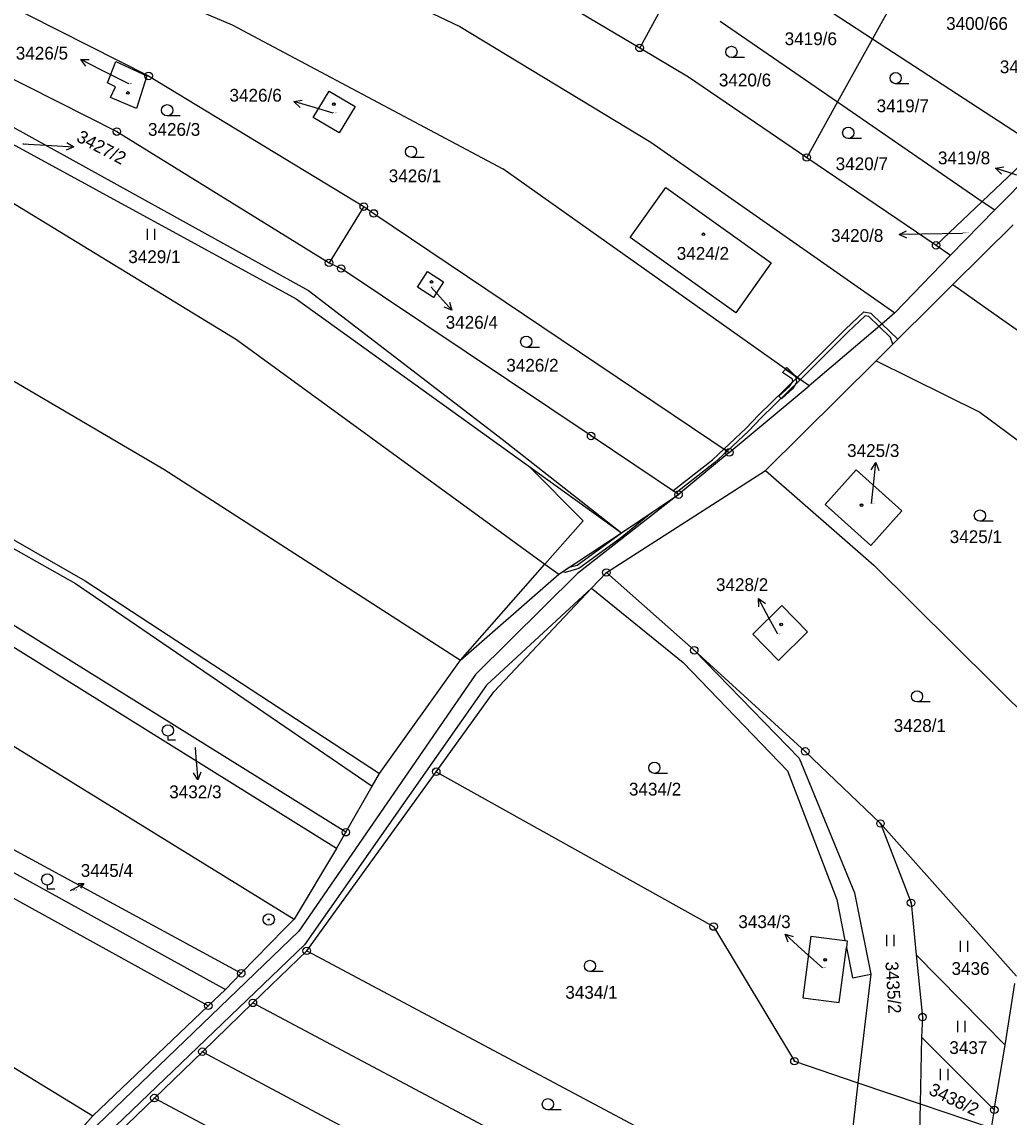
# Model space of a CAD drawing. Extents: x -593183 to -588034, y -1130415 to -1124994.
# Drawn here: x -592529.4 to -592398.1, y -1128913.5 to -1128767.8 of the extents above; entities that cross this region are included whole.
import ezdxf

# ---------------------------------------------------------------- set-up
doc = ezdxf.new("R2010")
doc.units = 0
for name, color, linetype in [('Vrstva 1', 7, 'Continuous'), ('Vrstva 16', 7, 'Continuous'), ('Vrstva 18', 7, 'Continuous'), ('Vrstva 19', 7, 'Continuous'), ('Vrstva 24', 7, 'Continuous'), ('Vrstva 25', 7, 'Continuous'), ('Vrstva 27', 7, 'Continuous'), ('Vrstva 4', 7, 'Continuous')]:
    doc.layers.add(name, color=color, linetype=linetype)

msp = doc.modelspace()

# ---------------------------------------------------------------- linework, layer by layer
at = {"layer": 'Vrstva 1'}
for p, q in [((-592517.32, -1128746.38), (-592471.18, -1128768.42)), ((-592542.34, -1128750.84), (-592501.44, -1128768.19)), ((-592409.73, -1128758.18), (-592416.3, -1128770.05)), ((-592465.21, -1128760.57), (-592447.25, -1128771.27)), ((-592431.6, -1128760.04), (-592416.3, -1128770.05)), ((-592539.2, -1128761.5), (-592512.55, -1128775)), ((-592443.17, -1128763.78), (-592447.25, -1128771.27)), ((-592501.44, -1128768.19), (-592465.44, -1128787.34)), ((-592436.57, -1128767.71), (-592420.95, -1128778.46)), ((-592543.19, -1128769.03), (-592516.78, -1128782.4)), ((-592471.18, -1128768.42), (-592445.79, -1128783.79)), ((-592447.25, -1128771.27), (-592440.76, -1128775.13)), ((-592416.3, -1128770.05), (-592420.95, -1128778.46)), ((-592416.3, -1128770.05), (-592394.15, -1128784.51)), ((-592518.04, -1128775.93), (-592516.93, -1128773.07)), ((-592516.93, -1128773.07), (-592512.81, -1128775)), ((-592512.81, -1128775), (-592514.17, -1128779.32)), ((-592512.55, -1128775), (-592483.94, -1128792.38)), ((-592440.76, -1128775.13), (-592425.03, -1128785.85)), ((-592555.76, -1128776.5), (-592500.87, -1128810.07)), ((-592516.97, -1128776.47), (-592518.04, -1128775.93)), ((-592517.63, -1128777.88), (-592516.97, -1128776.47)), ((-592490.66, -1128780.52), (-592488.53, -1128777.01)), ((-592488.53, -1128777.01), (-592485.08, -1128779.05)), ((-592514.17, -1128779.32), (-592517.63, -1128777.88)), ((-592420.95, -1128778.46), (-592425.03, -1128785.85)), ((-592420.95, -1128778.46), (-592401.7, -1128791.69)), ((-592485.08, -1128779.05), (-592487.21, -1128782.55)), ((-592532.71, -1128780.66), (-592491.3, -1128803.52)), ((-592487.21, -1128782.55), (-592490.66, -1128780.52)), ((-592533.66, -1128782.42), (-592492.95, -1128804.65)), ((-592516.78, -1128782.4), (-592488.56, -1128799.86)), ((-592445.79, -1128783.79), (-592413.31, -1128806.53)), ((-592425.03, -1128785.85), (-592407.83, -1128797.53)), ((-592394.15, -1128784.51), (-592401.7, -1128791.69)), ((-592400.03, -1128792.83), (-592392.75, -1128785.42)), ((-592424.73, -1128816.22), (-592465.44, -1128787.34)), ((-592448.53, -1128796.47), (-592443.79, -1128789.83)), ((-592443.79, -1128789.83), (-592429.77, -1128799.88)), ((-592483.94, -1128792.38), (-592488.56, -1128799.86)), ((-592483.94, -1128792.38), (-592482.62, -1128793.29)), ((-592401.7, -1128791.69), (-592407.83, -1128797.53)), ((-592405.92, -1128798.83), (-592400.03, -1128792.83)), ((-592401.7, -1128791.69), (-592400.03, -1128792.83)), ((-592482.62, -1128793.29), (-592435.34, -1128825.07)), ((-592397.6, -1128794.81), (-592405.6, -1128802.74)), ((-592434.47, -1128806.52), (-592448.53, -1128796.47)), ((-592405.92, -1128798.83), (-592413.31, -1128806.53)), ((-592407.83, -1128797.53), (-592405.92, -1128798.83)), ((-592488.56, -1128799.86), (-592486.95, -1128800.61)), ((-592429.77, -1128799.88), (-592434.47, -1128806.52)), ((-592453.71, -1128822.89), (-592486.95, -1128800.61)), ((-592476.8, -1128803.08), (-592475.48, -1128801.02)), ((-592475.48, -1128801.02), (-592473.33, -1128802.4)), ((-592474.65, -1128804.46), (-592476.8, -1128803.08)), ((-592473.33, -1128802.4), (-592474.65, -1128804.46)), ((-592405.6, -1128802.74), (-592415.81, -1128812.88)), ((-592405.6, -1128802.74), (-592400.89, -1128806.06)), ((-592492.95, -1128804.65), (-592461.98, -1128826.91)), ((-592491.3, -1128803.52), (-592465.54, -1128823.32)), ((-592400.89, -1128806.06), (-592398.94, -1128807.43)), ((-592581.35, -1128807.51), (-592520.98, -1128842.15)), ((-592413.31, -1128806.53), (-592414.73, -1128807.73)), ((-592398.94, -1128807.43), (-592379.51, -1128821.11)), ((-592414.73, -1128807.73), (-592424.73, -1128816.22)), ((-592500.87, -1128810.07), (-592459.85, -1128839.92)), ((-592537.54, -1128811.45), (-592510.51, -1128827.31)), ((-592430.52, -1128827.46), (-592415.81, -1128812.88)), ((-592415.81, -1128812.88), (-592402.02, -1128819.73)), ((-592435.34, -1128825.07), (-592424.73, -1128816.22)), ((-592402.02, -1128819.73), (-592383.41, -1128833.54)), ((-592465.54, -1128823.32), (-592449.66, -1128835.76)), ((-592442.08, -1128830.69), (-592453.71, -1128822.89)), ((-592435.34, -1128825.07), (-592442.08, -1128830.69)), ((-592510.51, -1128827.31), (-592471.08, -1128852.7)), ((-592461.98, -1128826.91), (-592449.66, -1128835.76)), ((-592451.68, -1128841.05), (-592430.52, -1128827.46)), ((-592430.52, -1128827.46), (-592416.11, -1128840.09)), ((-592422.59, -1128831.99), (-592418.47, -1128827.4)), ((-592418.47, -1128827.4), (-592412.39, -1128832.83)), ((-592449.66, -1128835.76), (-592442.08, -1128830.69)), ((-592416.52, -1128837.44), (-592422.59, -1128831.99)), ((-592412.39, -1128832.83), (-592416.52, -1128837.44)), ((-592458, -1128841.27), (-592449.66, -1128835.76)), ((-592459.85, -1128839.92), (-592458, -1128841.27)), ((-592453.66, -1128843.15), (-592451.68, -1128841.05)), ((-592451.68, -1128841.05), (-592440, -1128851.39)), ((-592416.11, -1128840.09), (-592391.31, -1128864.69)), ((-592520.98, -1128842.15), (-592481.87, -1128867.79)), ((-592471.08, -1128852.7), (-592458, -1128841.27)), ((-592466.66, -1128856.94), (-592453.66, -1128843.15)), ((-592453.66, -1128843.15), (-592441.48, -1128853.02)), ((-592591.74, -1128844.64), (-592500.24, -1128894.35)), ((-592432.22, -1128849.23), (-592428.36, -1128845.44)), ((-592428.36, -1128845.44), (-592424.92, -1128848.94)), ((-592487.57, -1128877.76), (-592537.79, -1128846.51)), ((-592428.78, -1128852.73), (-592432.22, -1128849.23)), ((-592424.92, -1128848.94), (-592428.78, -1128852.73)), ((-592440, -1128851.39), (-592425.23, -1128864.84)), ((-592481.87, -1128867.79), (-592471.08, -1128852.7)), ((-592441.48, -1128853.02), (-592427.59, -1128867.43)), ((-592545.7, -1128854.76), (-592493.21, -1128887.15)), ((-592474.31, -1128867.54), (-592466.66, -1128856.94)), ((-592568.22, -1128860.19), (-592502.35, -1128896.51)), ((-592504.62, -1128898.68), (-592569.67, -1128862.82)), ((-592425.23, -1128864.84), (-592415.23, -1128874.43)), ((-592491.53, -1128891.37), (-592474.31, -1128867.54)), ((-592482.84, -1128869.48), (-592481.87, -1128867.79)), ((-592474.31, -1128867.54), (-592437.42, -1128888.14)), ((-592427.59, -1128867.43), (-592421.03, -1128884.55)), ((-592486.33, -1128875.59), (-592482.84, -1128869.48)), ((-592415.23, -1128874.43), (-592397.15, -1128894.72)), ((-592415.23, -1128874.43), (-592411.16, -1128884.98)), ((-592487.57, -1128877.76), (-592486.33, -1128875.59)), ((-592487.57, -1128877.76), (-592493.21, -1128887.15)), ((-592421.03, -1128884.55), (-592419.96, -1128889.99)), ((-592411.16, -1128884.98), (-592410.47, -1128891.88)), ((-592494.52, -1128888.49), (-592493.21, -1128887.15)), ((-592500.24, -1128894.35), (-592494.52, -1128888.49)), ((-592437.42, -1128888.14), (-592426.67, -1128906.04)), ((-592424.49, -1128889.4), (-592425.56, -1128897.61)), ((-592424.49, -1128889.4), (-592419.96, -1128889.99)), ((-592419.96, -1128889.99), (-592419.65, -1128890.03)), ((-592419.65, -1128890.03), (-592419.77, -1128890.94)), ((-592498.69, -1128898.29), (-592491.53, -1128891.37)), ((-592491.53, -1128891.37), (-592436.93, -1128920.43)), ((-592420.72, -1128898.24), (-592419.77, -1128890.94)), ((-592419.77, -1128890.94), (-592418.97, -1128894.98)), ((-592410.47, -1128891.88), (-592398.65, -1128903.93)), ((-592410.47, -1128891.88), (-592409.64, -1128900.17)), ((-592502.35, -1128896.51), (-592500.24, -1128894.35)), ((-592418.97, -1128894.98), (-592416.52, -1128894.49)), ((-592416.52, -1128894.49), (-592418.22, -1128908.91)), ((-592504.62, -1128898.68), (-592502.35, -1128896.51)), ((-592398.65, -1128903.93), (-592397.37, -1128895.73)), ((-592425.56, -1128897.61), (-592420.72, -1128898.24)), ((-592544.73, -1128898.2), (-592519.97, -1128913.33)), ((-592519.97, -1128913.33), (-592504.62, -1128898.68)), ((-592505.41, -1128904.78), (-592498.69, -1128898.29)), ((-592498.69, -1128898.29), (-592440.66, -1128929.12)), ((-592409.64, -1128900.17), (-592409.78, -1128902.83)), ((-592409.78, -1128902.83), (-592409.96, -1128911.72)), ((-592409.78, -1128902.83), (-592400.1, -1128912.52)), ((-592511.79, -1128910.95), (-592505.41, -1128904.78)), ((-592505.41, -1128904.78), (-592427.88, -1128946.14)), ((-592400.1, -1128912.52), (-592398.65, -1128903.93)), ((-592426.67, -1128906.04), (-592418.22, -1128908.91)), ((-592418.22, -1128908.91), (-592420.6, -1128929.12)), ((-592418.22, -1128908.91), (-592409.96, -1128911.72)), ((-592517.81, -1128916.77), (-592511.79, -1128910.95)), ((-592511.79, -1128910.95), (-592431.99, -1128953.36)), ((-592409.96, -1128911.72), (-592410.03, -1128915.46)), ((-592409.96, -1128911.72), (-592400.53, -1128914.93)), ((-592400.1, -1128912.52), (-592400.53, -1128914.93)), ((-592525.77, -1128919.8), (-592519.97, -1128913.33))]:
    msp.add_line(p, q, dxfattribs=at)
msp.add_lwpolyline([(-592486.33, -1128875.59), (-592536.62, -1128844.3), (-592572.48, -1128825.37), (-592602.38, -1128811.32)], dxfattribs=at)
at = {"layer": 'Vrstva 16'}
for p, q in [((-592515.17, -1128776.05), (-592518.9, -1128774.17)), ((-592488.02, -1128779.95), (-592490.36, -1128779.26)), ((-592529.26, -1128784.01), (-592525.47, -1128784.24)), ((-592404.31, -1128795.94), (-592409.75, -1128796.05)), ((-592474.99, -1128803.09), (-592474.24, -1128803.92)), ((-592416.42, -1128831.88), (-592416.16, -1128829.41)), ((-592428.87, -1128849.26), (-592430.02, -1128847.15)), ((-592506.38, -1128864.34), (-592506.27, -1128865.64)), ((-592422.96, -1128893.64), (-592425.69, -1128891.18))]:
    msp.add_line(p, q, dxfattribs=at)
at = {"layer": 'Vrstva 24'}
for centre, radius in [((-592447.25, -1128771.27), 0.5), ((-592447.25, -1128771.27), 0.0327), ((-592512.55, -1128775), 0.5), ((-592512.55, -1128775), 0.0327), ((-592516.78, -1128782.4), 0.5), ((-592516.78, -1128782.4), 0.0327), ((-592425.03, -1128785.85), 0.5), ((-592425.03, -1128785.85), 0.0327), ((-592483.94, -1128792.38), 0.5), ((-592483.94, -1128792.38), 0.0327), ((-592482.62, -1128793.29), 0.5), ((-592482.62, -1128793.29), 0.0327), ((-592407.83, -1128797.53), 0.5), ((-592407.83, -1128797.53), 0.0327), ((-592488.56, -1128799.86), 0.5), ((-592488.56, -1128799.86), 0.0327), ((-592486.95, -1128800.61), 0.5), ((-592486.95, -1128800.61), 0.0327), ((-592453.71, -1128822.89), 0.5), ((-592453.71, -1128822.89), 0.0327), ((-592435.34, -1128825.07), 0.5), ((-592435.34, -1128825.07), 0.0327), ((-592442.08, -1128830.69), 0.5), ((-592442.08, -1128830.69), 0.0327), ((-592451.68, -1128841.05), 0.5), ((-592451.68, -1128841.05), 0.0327), ((-592440, -1128851.39), 0.5), ((-592440, -1128851.39), 0.0327), ((-592425.23, -1128864.84), 0.5), ((-592425.23, -1128864.84), 0.0327), ((-592474.31, -1128867.54), 0.5), ((-592474.31, -1128867.54), 0.0327), ((-592415.23, -1128874.43), 0.5), ((-592415.23, -1128874.43), 0.0327), ((-592486.33, -1128875.59), 0.5), ((-592486.33, -1128875.59), 0.0327), ((-592411.16, -1128884.98), 0.5), ((-592411.16, -1128884.98), 0.0327), ((-592496.58, -1128887.2), 0.75), ((-592496.58, -1128887.2), 0.0903), ((-592437.42, -1128888.14), 0.5), ((-592437.42, -1128888.14), 0.0327), ((-592491.53, -1128891.37), 0.5), ((-592491.53, -1128891.37), 0.0327), ((-592500.24, -1128894.35), 0.5), ((-592500.24, -1128894.35), 0.0327), ((-592498.69, -1128898.29), 0.5), ((-592504.62, -1128898.68), 0.5), ((-592504.62, -1128898.68), 0.0327), ((-592498.69, -1128898.29), 0.0327), ((-592409.64, -1128900.17), 0.5), ((-592409.64, -1128900.17), 0.0327), ((-592505.41, -1128904.78), 0.5), ((-592505.41, -1128904.78), 0.0327), ((-592426.67, -1128906.04), 0.5), ((-592426.67, -1128906.04), 0.0327), ((-592511.79, -1128910.95), 0.5), ((-592511.79, -1128910.95), 0.0327), ((-592400.1, -1128912.52), 0.5), ((-592400.1, -1128912.52), 0.0327)]:
    msp.add_circle(centre, radius, dxfattribs=at)
at = {"layer": 'Vrstva 25'}
for p, q in [((-592433.3, -1128772.56), (-592435.05, -1128772.56)), ((-592518.9, -1128774.17), (-592521.58, -1128772.82)), ((-592411.46, -1128776.03), (-592413.21, -1128776.03)), ((-592490.36, -1128779.26), (-592493.24, -1128778.42)), ((-592508.34, -1128780.32), (-592510.09, -1128780.32)), ((-592525.47, -1128784.24), (-592522.48, -1128784.42)), ((-592417.77, -1128783.32), (-592419.52, -1128783.32)), ((-592475.91, -1128785.84), (-592477.66, -1128785.84)), ((-592397.08, -1128788.21), (-592399.93, -1128787.28)), ((-592512.74, -1128795.32), (-592512.74, -1128796.82)), ((-592511.72, -1128796.82), (-592511.72, -1128795.32)), ((-592409.75, -1128796.05), (-592412.75, -1128796.11)), ((-592474.24, -1128803.92), (-592472.23, -1128806.14)), ((-592460.59, -1128811.1), (-592462.34, -1128811.1)), ((-592416.16, -1128829.41), (-592415.84, -1128826.43)), ((-592400.26, -1128834.22), (-592402.01, -1128834.22)), ((-592430.02, -1128847.15), (-592431.45, -1128844.51)), ((-592408.62, -1128858.27), (-592410.37, -1128858.27)), ((-592509.99, -1128862.8), (-592509.99, -1128863.3)), ((-592509.99, -1128863.3), (-592508.97, -1128863.3)), ((-592506.27, -1128865.64), (-592506.01, -1128868.63)), ((-592443.55, -1128867.76), (-592445.3, -1128867.76)), ((-592526.03, -1128882.62), (-592526.03, -1128883.12)), ((-592526.03, -1128883.12), (-592525.01, -1128883.12)), ((-592522.94, -1128883.35), (-592521.16, -1128882.42)), ((-592425.69, -1128891.18), (-592427.92, -1128889.17)), ((-592414.42, -1128889.25), (-592414.42, -1128890.75)), ((-592413.4, -1128890.75), (-592413.4, -1128889.25)), ((-592404.65, -1128890.02), (-592404.65, -1128891.52)), ((-592403.62, -1128891.52), (-592403.62, -1128890.02)), ((-592452.11, -1128894.12), (-592453.86, -1128894.12)), ((-592404.98, -1128900.69), (-592404.98, -1128902.19)), ((-592403.96, -1128902.19), (-592403.96, -1128900.69)), ((-592407.27, -1128907.07), (-592407.27, -1128908.57)), ((-592406.24, -1128908.57), (-592406.24, -1128907.07)), ((-592457.7, -1128912.53), (-592459.45, -1128912.53))]:
    msp.add_line(p, q, dxfattribs=at)
for points in [[(-592520.91, -1128773.72), (-592521.58, -1128772.82), (-592520.46, -1128772.82)], [(-592492.42, -1128779.18), (-592493.24, -1128778.42), (-592492.14, -1128778.22)], [(-592523.44, -1128783.86), (-592522.48, -1128784.42), (-592523.5, -1128784.86)], [(-592399.14, -1128788.07), (-592399.93, -1128787.28), (-592398.83, -1128787.11)], [(-592411.74, -1128796.59), (-592412.75, -1128796.11), (-592411.76, -1128795.59)], [(-592472.53, -1128805.07), (-592472.23, -1128806.14), (-592473.27, -1128805.74)], [(-592416.45, -1128827.37), (-592415.84, -1128826.43), (-592415.45, -1128827.47)], [(-592431.41, -1128845.63), (-592431.45, -1128844.51), (-592430.54, -1128845.15)], [(-592505.6, -1128867.59), (-592506.01, -1128868.63), (-592506.6, -1128867.68)], [(-592521.91, -1128882.43), (-592521.16, -1128882.42), (-592521.6, -1128883.03)], [(-592427.51, -1128890.21), (-592427.92, -1128889.17), (-592426.84, -1128889.47)]]:
    msp.add_lwpolyline(points, dxfattribs=at)
for centre, radius in [((-592435.05, -1128771.81), 0.75), ((-592413.21, -1128775.28), 0.75), ((-592515.3, -1128777.26), 0.175), ((-592515.3, -1128777.26), 0.15), ((-592510.09, -1128779.57), 0.75), ((-592487.93, -1128778.75), 0.175), ((-592487.93, -1128778.75), 0.15), ((-592419.52, -1128782.57), 0.75), ((-592477.66, -1128785.09), 0.75), ((-592438.78, -1128796.06), 0.175), ((-592438.78, -1128796.06), 0.15), ((-592474.94, -1128802.4), 0.175), ((-592474.94, -1128802.4), 0.15), ((-592462.34, -1128810.35), 0.75), ((-592417.74, -1128832.09), 0.175), ((-592417.74, -1128832.09), 0.15), ((-592402.01, -1128833.47), 0.75), ((-592428.42, -1128847.95), 0.175), ((-592428.42, -1128847.95), 0.15), ((-592410.37, -1128857.52), 0.75), ((-592509.99, -1128862.05), 0.75), ((-592445.3, -1128867.01), 0.75), ((-592526.03, -1128881.87), 0.75), ((-592453.86, -1128893.37), 0.75), ((-592422.59, -1128892.56), 0.175), ((-592422.59, -1128892.56), 0.15), ((-592459.45, -1128911.78), 0.75)]:
    msp.add_circle(centre, radius, dxfattribs=at)
at = {"layer": 'Vrstva 27'}
for p, q in [((-592419.88, -1128808.68), (-592417.43, -1128806.39)), ((-592417.27, -1128806.92), (-592419.54, -1128809.04)), ((-592417.43, -1128806.39), (-592416.53, -1128806.55)), ((-592416.77, -1128807.01), (-592417.27, -1128806.92)), ((-592415.42, -1128808.31), (-592416.77, -1128807.01)), ((-592416.53, -1128806.55), (-592415.03, -1128807.99)), ((-592426.31, -1128815.1), (-592419.88, -1128808.68)), ((-592419.54, -1128809.04), (-592425.89, -1128815.4)), ((-592415.42, -1128808.31), (-592415.03, -1128807.99)), ((-592415.03, -1128807.99), (-592415.42, -1128808.31)), ((-592413.88, -1128809.79), (-592415.42, -1128808.31)), ((-592415.03, -1128807.99), (-592412.92, -1128810.01)), ((-592413.58, -1128810.66), (-592413.88, -1128809.79)), ((-592412.92, -1128810.01), (-592413.58, -1128810.66)), ((-592428.25, -1128814.44), (-592427.87, -1128813.99)), ((-592426.94, -1128815.35), (-592428.25, -1128814.44)), ((-592427.87, -1128813.99), (-592427.67, -1128813.76)), ((-592426.48, -1128814.98), (-592427.87, -1128813.99)), ((-592427.87, -1128813.99), (-592426.48, -1128814.98)), ((-592427.67, -1128813.76), (-592426.48, -1128814.98)), ((-592426.48, -1128814.98), (-592426.38, -1128815.76)), ((-592431.42, -1128820.09), (-592426.31, -1128815.1)), ((-592425.89, -1128815.4), (-592431.06, -1128820.45)), ((-592428.74, -1128817.6), (-592427.33, -1128816.29)), ((-592427.33, -1128816.29), (-592426.9, -1128815.64)), ((-592426.38, -1128815.76), (-592426.95, -1128816.61)), ((-592426.9, -1128815.64), (-592426.94, -1128815.35)), ((-592426.31, -1128815.1), (-592425.89, -1128815.4)), ((-592425.89, -1128815.4), (-592426.31, -1128815.1)), ((-592428.4, -1128817.96), (-592428.74, -1128817.6)), ((-592426.95, -1128816.61), (-592428.4, -1128817.96)), ((-592433.13, -1128821.89), (-592431.42, -1128820.09)), ((-592431.06, -1128820.45), (-592432.77, -1128822.25)), ((-592436.03, -1128824.61), (-592433.13, -1128821.89)), ((-592432.77, -1128822.25), (-592435.6, -1128824.9)), ((-592437.56, -1128826.05), (-592436.03, -1128824.61)), ((-592435.6, -1128824.9), (-592437.24, -1128826.43)), ((-592436.03, -1128824.61), (-592435.6, -1128824.9)), ((-592435.6, -1128824.9), (-592436.03, -1128824.61)), ((-592442.84, -1128830.18), (-592437.56, -1128826.05)), ((-592437.24, -1128826.43), (-592442.4, -1128830.47)), ((-592442.4, -1128830.47), (-592442.84, -1128830.18)), ((-592445.68, -1128833.1), (-592449.84, -1128836.54)), ((-592449.66, -1128835.76), (-592445.68, -1128833.1)), ((-592455.57, -1128840.06), (-592449.66, -1128835.76)), ((-592449.84, -1128836.54), (-592455.35, -1128840.52)), ((-592457.52, -1128840.95), (-592456.61, -1128840.35)), ((-592457.17, -1128841.03), (-592457.52, -1128840.95)), ((-592455.35, -1128840.52), (-592457.17, -1128841.03)), ((-592456.61, -1128840.35), (-592455.57, -1128840.06))]:
    msp.add_line(p, q, dxfattribs=at)
at = {"layer": 'Vrstva 4'}
for p, q in [((-592576.48, -1128812.11), (-592522.27, -1128842.49)), ((-592461.98, -1128826.91), (-592454.78, -1128834.16)), ((-592442.08, -1128830.69), (-592455.51, -1128841.18)), ((-592459.85, -1128839.92), (-592454.78, -1128834.16)), ((-592471.08, -1128852.7), (-592459.85, -1128839.92)), ((-592455.51, -1128841.18), (-592469.07, -1128854.63)), ((-592522.27, -1128842.49), (-592482.84, -1128869.48)), ((-592453.66, -1128843.15), (-592467.63, -1128856.01)), ((-592440, -1128851.39), (-592426.04, -1128865.73)), ((-592469.07, -1128854.63), (-592492.58, -1128888.73)), ((-592467.63, -1128856.01), (-592491.84, -1128890.59)), ((-592426.04, -1128865.73), (-592418.7, -1128883.64)), ((-592418.7, -1128883.64), (-592416.52, -1128894.49)), ((-592492.58, -1128888.73), (-592525.26, -1128920.17)), ((-592491.84, -1128890.59), (-592524.27, -1128921.66))]:
    msp.add_line(p, q, dxfattribs=at)

# ---------------------------------------------------------------- texts
at = {"layer": 'Vrstva 16'}
for s, p in [('3426/5', (-592530.22, -1128772.82)), ('3400/75', (-592399.36, -1128774.63)), ('3426/6', (-592501.8, -1128778.42)), ('3419/8', (-592407.59, -1128786.75)), ('3420/8', (-592421.8, -1128797.07)), ('3426/4', (-592473.05, -1128808.62)), ('3425/3', (-592419.67, -1128825.68)), ('3428/2', (-592437.11, -1128843.51)), ('3432/3', (-592509.81, -1128871.07)), ('3445/4', (-592521.58, -1128881.53)), ('3434/3', (-592434.13, -1128888.34))]:
    msp.add_text(s, height=1.7, dxfattribs=at).set_placement(p)
msp.add_text('3427/2', height=1.7, rotation=332.1077, dxfattribs=at).set_placement((-592522.28, -1128783.62))
at = {"layer": 'Vrstva 18'}
for s, height, p in [('3400/66', 1.7, (-592406.5, -1128768.88)), ('3419/6', 1.7, (-592427.97, -1128770.9)), ('3420/6', 1.7, (-592436.72, -1128776.39)), ('3419/7', 1.7, (-592415.74, -1128779.82)), ('3426/3', 1.7, (-592512.64, -1128782.96)), ('3427/2', 0.1, (-592529.26, -1128784.01)), ('3420/7', 1.7, (-592421.19, -1128787.53)), ('3426/1', 1.7, (-592480.62, -1128789.13)), ('3420/8', 0.2, (-592404.31, -1128795.94)), ('3429/1', 1.7, (-592515.26, -1128799.89)), ('3426/2', 1.7, (-592464.99, -1128814.33)), ('3425/1', 1.7, (-592406.02, -1128837.13)), ('3428/1', 1.7, (-592413.47, -1128862.25)), ('3432/3', 0.1, (-592506.61, -1128864.34)), ('3434/2', 1.7, (-592448.68, -1128870.71)), ('3445/4', 0.2, (-592522.94, -1128883.35)), ('3436', 1.7, (-592405.78, -1128894.57)), ('3434/1', 1.7, (-592457.14, -1128897.74)), ('3437', 1.7, (-592406.07, -1128905.09))]:
    msp.add_text(s, height=height, dxfattribs=at).set_placement(p)
for s, rotation, p in [('3435/2', 273.446, (-592414.58, -1128892.83)), ('3438/2', 334.5899, (-592408.94, -1128910.4))]:
    msp.add_text(s, height=1.7, rotation=rotation, dxfattribs=at).set_placement(p)
at = {"layer": 'Vrstva 19'}
for s, height, p in [('3426/5', 0.1, (-592515.17, -1128776.05)), ('3426/6', 0.1, (-592488.02, -1128779.95)), ('3424/2', 1.7, (-592442.32, -1128799.45)), ('3426/4', 0.1, (-592474.99, -1128803.09)), ('3425/3', 0.1, (-592416.42, -1128831.88)), ('3428/2', 0.1, (-592428.87, -1128849.26)), ('3434/3', 0.1, (-592422.96, -1128893.64))]:
    msp.add_text(s, height=height, dxfattribs=at).set_placement(p)

doc.saveas('drawing.dxf')
